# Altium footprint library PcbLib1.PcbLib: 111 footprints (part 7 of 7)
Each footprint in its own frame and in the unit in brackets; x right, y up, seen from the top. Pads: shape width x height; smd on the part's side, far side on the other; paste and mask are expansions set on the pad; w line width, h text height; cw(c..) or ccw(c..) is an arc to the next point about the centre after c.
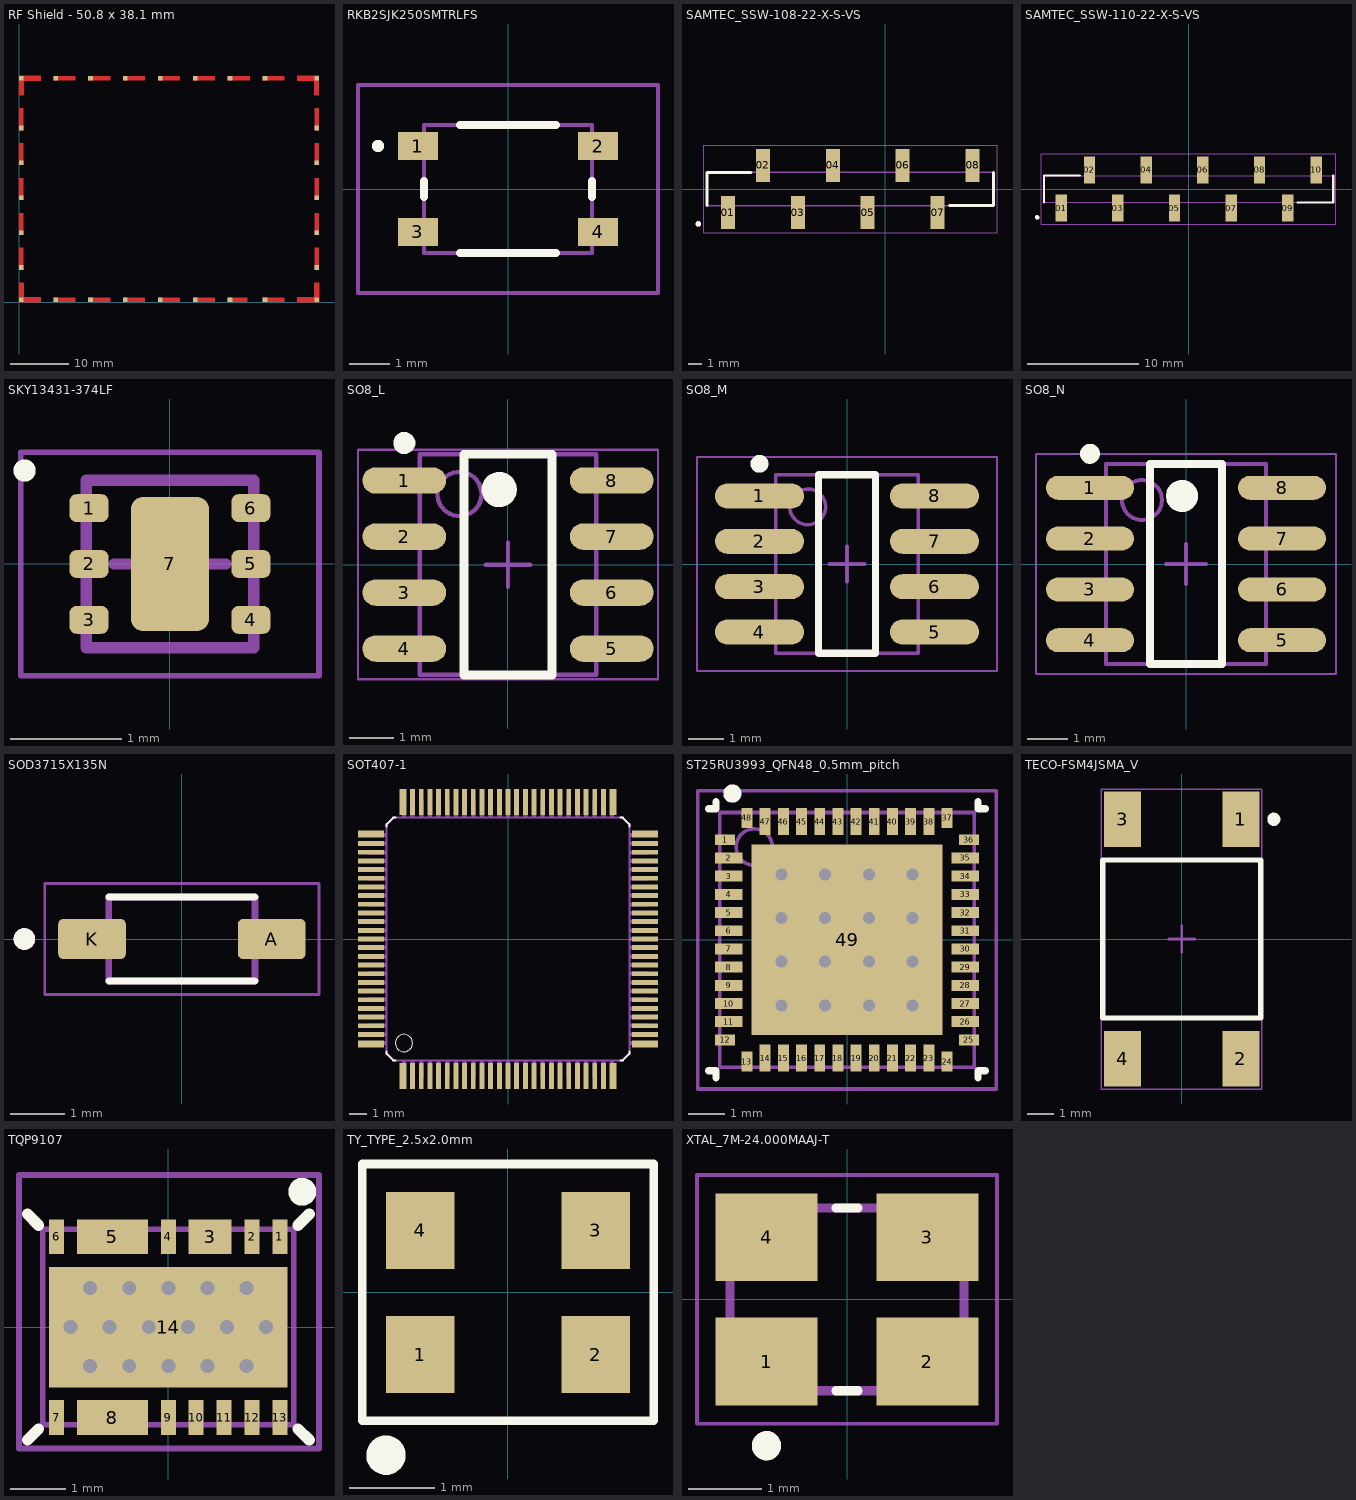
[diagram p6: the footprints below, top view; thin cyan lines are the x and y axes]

## RF Shield - 50.8 x 38.1 mm [mm] "2118732-2"
height 5.08
pads (28):
  rect 0.8x0.8 smd: 1(0.4,0.4) 2(0.4,5.95) 3(0.4,11.95) 4(0.4,17.95) 5(0.4,23.95) 6(0.4,29.95) 7(0.4,38.5) 8(6.3,38.5) 9(12.3,38.5) 10(18.3,38.5) 11(24.3,38.5) 12(30.3,38.5) 13(36.3,38.5) 14(42.3,38.5) 15(51.2,38.5) 16(51.2,29.95) 17(51.2,23.95) 18(51.2,17.95) 19(51.2,11.95) 20(51.2,5.95) 21(51.2,0.4) 22(42.3,0.4) 23(36.3,0.4) 24(30.3,0.4) 25(24.3,0.4) 26(18.3,0.4) 27(12.3,0.4) 28(6.3,0.4)
Top Layer:
  rectangle: 35.9,38.1 39.7,38.9
  rectangle: 29.9,38.1 33.7,38.9
  rectangle: 23.9,38.1 27.7,38.9
  rectangle: 17.9,38.1 21.7,38.9
  rectangle: 11.9,38.1 15.7,38.9
  rectangle: 5.9,38.1 9.7,38.9
  rectangle: 41.9,38.1 45.7,38.9
  rectangle: 50.8,29.55 51.6,33.35
  rectangle: 50.8,23.55 51.6,27.35
  rectangle: 50.8,17.55 51.6,21.35
  rectangle: 50.8,11.55 51.6,15.35
  rectangle: 50.8,5.55 51.6,9.35
  rectangle: 41.9,0 45.7,0.8
  rectangle: 0,23.55 0.8,27.35
  rectangle: 0,17.55 0.8,21.35
  rectangle: 0,11.55 0.8,15.35
  rectangle: 0,5.55 0.8,9.35
  rectangle: 5.9,0 9.7,0.8
  rectangle: 11.9,0 15.7,0.8
  rectangle: 17.9,0 21.7,0.8
  rectangle: 23.9,0 27.7,0.8
  rectangle: 29.9,0 33.7,0.8
  rectangle: 35.9,0 39.3,0.8
  rectangle: 0,29.55 0.8,33.35
  region: 51.6,38.899 51.6,35.55 50.8,35.55 50.8,38.1 47.899,38.1 47.899,38.899
  region: 51.6,0 51.6,3.3 50.8,3.3 50.8,0.8 47.9,0.8 47.9,0
  region: 0,0 0,3.35 0.8,3.35 0.8,0.8 3.7,0.8 3.7,0
  region: 0,38.9 0,35.55 0.8,35.55 0.8,38.1 3.701,38.1 3.701,38.9
3D body: height 5.08, standoff 4.88, extent 1.9,18.8 2.9,19.45
3D body: height 5.08, standoff 4.88, extent 1.9,19.45 2.9,20.1
3D body: height 5.08, standoff 4.88, extent 25.8,36 26.45,37
3D body: height 5.08, standoff 4.88, extent 25.15,36 25.8,37
3D body: height 5.08, standoff 4.88, extent 25.15,1.9 25.8,2.9
3D body: height 5.08, standoff 4.88, extent 25.8,1.9 26.45,2.9
3D body: height 5.08, standoff 4.88, extent 48.7,18.8 49.7,19.45
3D body: height 5.08, standoff 4.88, extent 48.7,19.45 49.7,20.1
3D body: height 5.08, standoff 4.88, extent 2.9,18.8 48.7,20.1
3D body: height 5.08, standoff 4.88, extent 25.15,2.9 26.45,36
3D body: height 5.08, standoff 4.88, extent 47.4,0.6 51,4.2
3D body: height 5.08, standoff 4.88, extent 47.4,34.7 51,38.3
3D body: height 5.08, standoff 4.88, extent 0.6,34.7 4.2,38.3
3D body: height 5.08, standoff 4.88, extent 0.6,1.9 1.9,37
3D body: height 5.08, standoff 4.88, extent 49.7,2.187 51,37
3D body: height 5.08, standoff 4.88, extent 0.6,37 51,38.3
3D body: height 5.08, standoff 4.88, extent 0.6,0.6 49.425,1.9
3D body: height 5.08, standoff 4.88, extent 0.6,0.6 4.2,4.2
3D body: height 0.51, standoff 0, extent 51,5.95 51.2,8.95
3D body: height 0.51, standoff 0, extent 51,11.95 51.2,14.95
3D body: height 0.51, standoff 0, extent 51,17.95 51.2,20.95
3D body: height 0.51, standoff 0, extent 51,23.95 51.2,26.95
3D body: height 0.51, standoff 0, extent 51,29.95 51.2,32.95
3D body: height 0.51, standoff 0, extent 50.999,35.95 51.199,38.5
3D body: height 0.51, standoff 0, extent 51,0.4 51.2,2.95
3D body: height 5.08, standoff 0.5, extent 51,0.4 51.2,38.5
3D body: height 5.08, standoff 0.5, extent 0.4,0.4 0.6,38.5
3D body: height 0.51, standoff 0, extent 0.4,0.4 0.6,2.95
3D body: height 0.51, standoff 0, extent 0.401,35.95 0.601,38.5
3D body: height 0.51, standoff 0, extent 0.4,29.95 0.6,32.95
3D body: height 0.51, standoff 0, extent 0.4,23.95 0.6,26.95
3D body: height 0.51, standoff 0, extent 0.4,17.95 0.6,20.95
3D body: height 0.51, standoff 0, extent 0.4,11.95 0.6,14.95
3D body: height 0.51, standoff 0, extent 0.4,5.95 0.6,8.95
3D body: height 5.08, standoff 0.5, extent 0.4,38.3 51.2,38.5
3D body: height 0.51, standoff 0, extent 0.4,38.3 3.3,38.5
3D body: height 0.51, standoff 0, extent 48.3,38.3 51.2,38.5
3D body: height 0.51, standoff 0, extent 6.3,38.3 9.3,38.5
3D body: height 0.51, standoff 0, extent 12.3,38.3 15.3,38.5
3D body: height 0.51, standoff 0, extent 18.3,38.3 21.3,38.5
3D body: height 0.51, standoff 0, extent 24.3,38.3 27.3,38.5
3D body: height 0.51, standoff 0, extent 30.3,38.3 33.3,38.5
3D body: height 0.51, standoff 0, extent 35.9,38.3 38.9,38.5
3D body: height 0.51, standoff 0, extent 42.3,38.3 45.3,38.5
3D body: height 0.51, standoff 0, extent 42.3,0.4 45.3,0.6
3D body: height 0.51, standoff 0, extent 35.9,0.4 38.9,0.6
3D body: height 0.51, standoff 0, extent 30.3,0.4 33.3,0.6
3D body: height 0.51, standoff 0, extent 24.3,0.4 27.3,0.6
3D body: height 0.51, standoff 0, extent 18.3,0.4 21.3,0.6
3D body: height 0.51, standoff 0, extent 12.3,0.4 15.3,0.6
3D body: height 0.51, standoff 0, extent 6.3,0.4 9.3,0.6
3D body: height 0.51, standoff 0, extent 48.3,0.4 51.2,0.6
3D body: height 0.51, standoff 0, extent 0.4,0.4 3.3,0.6
3D body: height 5.08, standoff 0.5, extent 0.4,0.4 51.2,0.6
3D body: height 5.08, standoff 4.88, extent 22.8,16.45 28.8,22.45
3D body: height 5.08, standoff 4.88, extent 49.425,0.6 51,2.187

## RKB2SJK250SMTRLFS [mm]
pads (4):
  rect 1x0.7 smd: 1(-2.25,1.075) 2(2.25,1.075) 3(-2.25,-1.075) 4(2.25,-1.075)
Top Overlay:
  lines w0.2: -3.3,1.075 ccw(c-3.25,1.075) -3.2,1.075 ; -3.3,1.075 cw(c-3.25,1.075) -3.2,1.075 ; -3.3,1.075 ccw(c-3.25,1.075) -3.2,1.075 ; -2.1,-0.2 -2.1,0.2 -2.1,-0.2 ; -1.2,-1.6 1.2,-1.6 -1.2,-1.6 ; -1.2,1.6 1.2,1.6 -1.2,1.6 ; 2.1,-0.2 2.1,0.2 2.1,-0.2
Mechanical 13:
  lines w0.1: -2.1,-1.6 2.1,-1.6 2.1,1.6 -2.1,1.6 -2.1,-1.6
Mechanical 15:
  lines w0.1: -3.75,-2.6 3.75,-2.6 3.75,2.6 -3.75,2.6 -3.75,-2.6
3D body "RKB2SJK250SMTR_LFS.stp": height 2.8, standoff 0, extent -2.68,-1.6 2.68,1.6

## SAMTEC_SSW-108-22-X-S-VS [mm]
pads (8):
  rect 1.02x2.41 smd: 01(-11.43,-1.715) 02(-8.89,1.715) 03(-6.35,-1.715) 04(-3.81,1.715) 05(-1.27,-1.715) 06(1.27,1.715) 07(3.81,-1.715) 08(6.35,1.715)
Top Overlay:
  circle w0.2: c-13.58,-2.54 r0.1
  lines w0.2: -12.955,-1.205 -12.955,1.205 -9.75,1.205 ; 4.67,-1.205 7.875,-1.205 7.875,1.205
Mechanical 13:
  circle w0.2: c-13.58,-2.54 r0.1
  lines w0.1: -12.955,-1.205 7.874,-1.205 7.874,1.205 -12.955,1.205 -12.955,-1.205
Mechanical 15:
  lines w0.05: -13.205,-3.17 8.128,-3.17 8.128,3.17 -13.205,3.17 -13.205,-3.17
3D body "SSW-108-22-F-S-VS.stp": height 9.76, standoff -0.02, extent -12.954,-2.578 7.874,2.578

## SAMTEC_SSW-110-22-X-S-VS [mm]
pads (10):
  rect 1.02x2.41 smd: 01(-11.43,-1.715) 02(-8.89,1.715) 03(-6.35,-1.715) 04(-3.81,1.715) 05(-1.27,-1.715) 06(1.27,1.715) 07(3.81,-1.715) 08(6.35,1.715) 09(8.89,-1.715) 10(11.43,1.715)
Top Overlay:
  circle w0.2: c-13.58,-2.54 r0.1
  lines w0.2: -12.955,-1.205 -12.955,1.205 -9.75,1.205 ; 9.75,-1.205 12.955,-1.205 12.955,1.205
Mechanical 13:
  circle w0.2: c-13.58,-2.54 r0.1
  lines w0.1: -12.955,-1.205 12.955,-1.205 12.955,1.205 -12.955,1.205 -12.955,-1.205
Mechanical 15:
  lines w0.05: -13.205,-3.17 13.205,-3.17 13.205,3.17 -13.205,3.17 -13.205,-3.17

## SKY13431-374LF [mm] "6 Pin DFN"
height 0.5
pads (7):
  rrect50% 0.35x0.25 smd mask+0.05: 1(-0.725,0.5) 2(-0.725,0) 3(-0.725,-0.5) 4(0.725,-0.5) 5(0.725,0) 6(0.725,0.5)
  rrect30% 0.7x1.2 smd mask+0.05: 7(0,0)
Top Overlay:
  circle w0.1: c-1.302,0.837 r0.05
Mechanical 13:
  lines w0.1: -0.75,-0.75 -0.75,0.75 0.75,0.75 0.75,-0.75 -0.75,-0.75
Mechanical 15:
  lines w0.05: -1.335,-1 -1.335,1 1.335,1 1.335,-1 -1.335,-1
  lines w0.1: -0.5,0 0.5,0 ; 0,-0.5 0,0.5
3D body: height 0.5, standoff 0, extent -0.75,-0.75 0.75,0.75

## SO8_L [mm] "SOIC, 8-Leads, Body 4.9x3.9mm, Pitch 1.27mm, IPC High Density"
height 1.75
pads (8):
  oval 1.9x0.6 smd: 1(-2.35,1.905) 2(-2.35,0.635) 3(-2.35,-0.635) 4(-2.35,-1.905) 5(2.35,-1.905) 6(2.35,-0.635) 7(2.35,0.635) 8(2.35,1.905)
Top Overlay:
  circle w0.4: c-0.2,1.7 r0.2
  circle w0.25: c-2.35,2.755 r0.125
  lines w0.2: -1,-2.5 1,-2.5 1,2.5 -1,2.5 -1,-2.5
Mechanical 13:
  circle w0.1: c-1.1,1.6 r0.5
  lines w0.1: -2,-2.5 2,-2.5 2,2.5 -2,2.5 -2,-2.5
Mechanical 15:
  lines w0.05: -3.4,-2.6 3.4,-2.6 3.4,2.6 -3.4,2.6 -3.4,-2.6
  lines w0.1: -0.5,0 0.5,0 ; 0,-0.5 0,0.5
3D body: height 1.75, standoff 0.1, extent -2,-2.5 2,2.5

## SO8_M [mm] "SOIC, 8-Leads, Body 4.9x3.9mm, Pitch 1.27mm, IPC Low Density"
height 1.75
pads (8):
  oval 2.5x0.7 smd: 1(-2.45,1.905) 2(-2.45,0.635) 3(-2.45,-0.635) 4(-2.45,-1.905) 5(2.45,-1.905) 6(2.45,-0.635) 7(2.45,0.635) 8(2.45,1.905)
Top Overlay:
  circle w0.25: c-2.45,2.805 r0.125
  lines w0.2: -0.8,-2.5 -0.8,2.5 0.8,2.5 0.8,-2.5 -0.8,-2.5
Mechanical 13:
  circle w0.1: c-1.1,1.6 r0.5
  lines w0.1: -2,-2.5 -2,2.5 2,2.5 2,-2.5 -2,-2.5
Mechanical 15:
  lines w0.05: -4.2,-3 -4.2,3 4.2,3 4.2,-3 -4.2,-3
  lines w0.1: -0.5,0 0.5,0 ; 0,-0.5 0,0.5
3D body: height 1.75, standoff 0.1, extent -2,-2.5 2,2.5

## SO8_N [mm] "SOIC, 8-Leads, Body 4.9x3.9mm, Pitch 1.27mm, IPC Medium Density"
height 1.75
pads (8):
  oval 2.2x0.6 smd: 1(-2.4,1.905) 2(-2.4,0.635) 3(-2.4,-0.635) 4(-2.4,-1.905) 5(2.4,-1.905) 6(2.4,-0.635) 7(2.4,0.635) 8(2.4,1.905)
Top Overlay:
  circle w0.4: c-0.1,1.7 r0.2
  circle w0.25: c-2.4,2.755 r0.125
  lines w0.2: -0.9,-2.5 0.9,-2.5 0.9,2.5 -0.9,2.5 -0.9,-2.5
Mechanical 13:
  circle w0.1: c-1.1,1.6 r0.5
  lines w0.1: -2,-2.5 2,-2.5 2,2.5 -2,2.5 -2,-2.5
Mechanical 15:
  lines w0.05: -3.75,-2.75 3.75,-2.75 3.75,2.75 -3.75,2.75 -3.75,-2.75
  lines w0.1: -0.5,0 0.5,0 ; 0,-0.5 0,0.5
3D body: height 1.75, standoff 0.1, extent -2,-2.5 2,2.5

## SOD3715X135N [mm]
pads (2):
  rrect25% 1.25x0.74 smd: A(1.66,0) K(-1.66,0)
Top Overlay:
  circle w0.2: c-2.91,0 r0.1
  lines w0.127: -1.35,-0.775 1.35,-0.775 ; -1.35,0.775 1.35,0.775
Mechanical 13:
  circle w0.2: c-2.91,0 r0.1
  lines w0.127: -1.35,-0.775 1.35,-0.775 1.35,0.775 -1.35,0.775 -1.35,-0.775
Mechanical 15:
  lines w0.05: -2.535,-1.025 2.535,-1.025 2.535,1.025 -2.535,1.025 -2.535,-1.025
3D body "BAT54W-HG3-18.STEP": height 1.41, standoff -0.04, extent -1.85,-0.775 1.85,0.775

## SOT407-1 [mm]
pads (100):
  rect 0.4x1.5 smd: 1(-6.06,-7.9) 25(6.06,-7.9) 51(6.06,7.9) 75(-6.06,7.9)
  rect 0.28x1.5 smd: 2(-5.5,-7.9) 3(-5,-7.9) 4(-4.5,-7.9) 5(-4,-7.9) 6(-3.5,-7.9) 7(-3,-7.9) 8(-2.5,-7.9) 9(-2,-7.9) 10(-1.5,-7.9) 11(-1,-7.9) 12(-0.5,-7.9) 13(0,-7.9) 14(0.5,-7.9) 15(1,-7.9) 16(1.5,-7.9) 17(2,-7.9) 18(2.5,-7.9) 19(3,-7.9) 20(3.5,-7.9) 21(4,-7.9) 22(4.5,-7.9) 23(5,-7.9) 24(5.5,-7.9) 52(5.5,7.9) 53(5,7.9) 54(4.5,7.9) 55(4,7.9) 56(3.5,7.9) 57(3,7.9) 58(2.5,7.9) 59(2,7.9) 60(1.5,7.9) 61(1,7.9) 62(0.5,7.9) 63(0,7.9) 64(-0.5,7.9) 65(-1,7.9) 66(-1.5,7.9) 67(-2,7.9) 68(-2.5,7.9) 69(-3,7.9) 70(-3.5,7.9) 71(-4,7.9) 72(-4.5,7.9) 73(-5,7.9) 74(-5.5,7.9)
  rect 1.5x0.4 smd: 26(7.9,-6.06) 50(7.9,6.06) 76(-7.9,6.06) 100(-7.9,-6.06)
  rect 1.5x0.28 smd: 27(7.9,-5.5) 28(7.9,-5) 29(7.9,-4.5) 30(7.9,-4) 31(7.9,-3.5) 32(7.9,-3) 33(7.9,-2.5) 34(7.9,-2) 35(7.9,-1.5) 36(7.9,-1) 37(7.9,-0.5) 38(7.9,0) 39(7.9,0.5) 40(7.9,1) 41(7.9,1.5) 42(7.9,2) 43(7.9,2.5) 44(7.9,3) 45(7.9,3.5) 46(7.9,4) 47(7.9,4.5) 48(7.9,5) 49(7.9,5.5) 77(-7.9,5.5) 78(-7.9,5) 79(-7.9,4.5) 80(-7.9,4) 81(-7.9,3.5) 82(-7.9,3) 83(-7.9,2.5) 84(-7.9,2) 85(-7.9,1.5) 86(-7.9,1) 87(-7.9,0.5) 88(-7.9,0) 89(-7.9,-0.5) 90(-7.9,-1) 91(-7.9,-1.5) 92(-7.9,-2) 93(-7.9,-2.5) 94(-7.9,-3) 95(-7.9,-3.5) 96(-7.9,-4) 97(-7.9,-4.5) 98(-7.9,-5) 99(-7.9,-5.5)
Top Overlay:
  circle w0: c-6,-6 r0.5
  lines w0.127: -7,-6.5 -7,-6.625 -6.625,-7 -6.5,-7 ; -7,6.5 -7,6.625 -6.625,7 -6.5,7 ; 6.5,-7 6.625,-7 7,-6.625 7,-6.5 ; 6.5,7 6.625,7 7,6.625 7,6.5
Mechanical 13:
  drawing of 108 lines, arcs and shapes, not listed
3D body "step_temp.STEP": height 0.75, standoff -0.95, extent -8,-8 8,8

## ST25RU3993_QFN48_0.5mm_pitch [mm] "QFN, 48-Leads, Body 7,0x7,0mm (max), Pitch 0,50mm, IPC Medium Density"
height 1
pads (49):
  rect 0.55x0.3 smd paste+0 mask+0.05: 1(-3.35,2.75) 12(-3.35,-2.75) 25(3.35,-2.75) 36(3.35,2.75)
  rect 0.75x0.3 smd mask+0.05: 2(-3.25,2.25)
  rect 0.75x0.3 smd paste+0 mask+0.05: 3(-3.25,1.75) 4(-3.25,1.25) 5(-3.25,0.75) 6(-3.25,0.25) 7(-3.25,-0.25) 8(-3.25,-0.75) 9(-3.25,-1.25) 10(-3.25,-1.75) 11(-3.25,-2.25) 26(3.25,-2.25) 27(3.25,-1.75) 28(3.25,-1.25) 29(3.25,-0.75) 30(3.25,-0.25) 31(3.25,0.25) 32(3.25,0.75) 33(3.25,1.25) 34(3.25,1.75) 35(3.25,2.25)
  rect 0.3x0.55 smd paste+0 mask+0.05: 13(-2.75,-3.35) 24(2.75,-3.35) 37(2.75,3.35) 48(-2.75,3.35)
  rect 0.3x0.75 smd paste+0 mask+0.05: 14(-2.25,-3.25) 15(-1.75,-3.25) 16(-1.25,-3.25) 17(-0.75,-3.25) 18(-0.25,-3.25) 19(0.25,-3.25) 20(0.75,-3.25) 21(1.25,-3.25) 22(1.75,-3.25) 23(2.25,-3.25) 38(2.25,3.25) 39(1.75,3.25) 40(1.25,3.25) 41(0.75,3.25) 42(0.25,3.25) 43(-0.25,3.25) 44(-0.75,3.25) 45(-1.25,3.25) 46(-1.75,3.25) 47(-2.25,3.25)
  rect 5.24x5.24 smd mask+0.07: 49(0,0)
via -1.8,-0.6 diameter 0.66 hole 0.33
via -0.6,-0.6 diameter 0.66 hole 0.33
via 0.6,-0.6 diameter 0.66 hole 0.33
via 1.8,-0.6 diameter 0.66 hole 0.33
via -1.8,-1.8 diameter 0.66 hole 0.33
via -0.6,-1.8 diameter 0.66 hole 0.33
via 0.6,-1.8 diameter 0.66 hole 0.33
via 1.8,-1.8 diameter 0.66 hole 0.33
via -0.6,1.8 diameter 0.66 hole 0.33
via 0.6,1.8 diameter 0.66 hole 0.33
via -1.8,1.8 diameter 0.66 hole 0.33
via 1.8,0.6 diameter 0.66 hole 0.33
via 0.6,0.6 diameter 0.66 hole 0.33
via -0.6,0.6 diameter 0.66 hole 0.33
via -1.8,0.6 diameter 0.66 hole 0.33
via 1.8,1.8 diameter 0.66 hole 0.33
Top Overlay:
  circle w0.25: c-3.15,4.021 r0.125
  lines w0.2: -3.8,-3.6 -3.6,-3.6 -3.6,-3.8 ; -3.8,3.6 -3.6,3.6 -3.6,3.8 ; 3.6,-3.8 3.6,-3.6 3.8,-3.6 ; 3.6,3.8 3.6,3.6 3.8,3.6
Mechanical 13:
  circle w0.1: c-2.55,2.55 r0.5
  lines w0.1: -3.5,-3.5 -3.5,3.5 3.5,3.5 3.5,-3.5 -3.5,-3.5
Mechanical 15:
  lines w0.1: -0.5,0 0.5,0 ; 0,-0.5 0,0.5 ; -4.1,-4.1 -4.1,4.1 4.1,4.1 4.1,-4.1 -4.1,-4.1
3D body "as3993.stp": height 0.9, standoff 0, extent -3.503,-3.503 3.503,3.503
3D body: height 1, standoff 0, extent -3.495,-3.494 3.488,3.493

## TECO-FSM4JSMA_V [mm] "SMD, 4-Leads, Body 6x6mm, Pitch 4.5mm"
height 5.23
pads (4):
  rect 1.4x2.1 smd: 1(2.25,4.55) 2(2.25,-4.55) 3(-2.25,4.55) 4(-2.25,-4.55)
Top Overlay:
  circle w0.25: c3.5,4.55 r0.125
  lines w0.2: -3,-3 3,-3 3,3 -3,3 -3,-3
Mechanical 13:
  lines w0.1: -3,-3 -3,3 3,3 3,-3 -3,-3
Mechanical 15:
  lines w0.05: -3.05,-5.7 -3.05,5.7 3.05,5.7 3.05,-5.7 -3.05,-5.7
  lines w0.1: -0.5,0 0.5,0 ; 0,-0.5 0,0.5
3D body "c-4-1437565-2-s-3d.stp": height 5.08, standoff 0, extent -3,-5 3,5

## TQP9107 [mm] "699 – 960 MHz 2-stage Power Amplifier"
height 1
pads (14):
  rect 0.27x0.62 smd mask+0.05: 1(2,1.62) 2(1.5,1.62) 4(0,1.62) 6(-2,1.62) 7(-2,-1.62) 9(0,-1.62) 10(0.5,-1.62) 11(1,-1.62) 12(1.5,-1.62) 13(2,-1.62)
  rect 0.77x0.62 smd mask+0.05: 3(0.75,1.62)
  rect 1.27x0.62 smd mask+0.05: 5(-1,1.62) 8(-1,-1.62)
  rect 4.28x2.16 smd mask+0.05: 14(0,0)
via 1.4,-0.7 diameter 0.6 hole 0.25
via 1.4,0.7 diameter 0.6 hole 0.25
via 0.7,0.7 diameter 0.6 hole 0.25
via 0.7,-0.7 diameter 0.6 hole 0.25
via -1.4,-0.7 diameter 0.6 hole 0.25
via -0.7,-0.7 diameter 0.6 hole 0.25
via -1.4,0.7 diameter 0.6 hole 0.25
via -0.7,0.7 diameter 0.6 hole 0.25
via -1.75,0 diameter 0.6 hole 0.25
via -1.05,0 diameter 0.6 hole 0.25
via 1.75,0 diameter 0.6 hole 0.25
via 0,0.7 diameter 0.6 hole 0.25
via 0,-0.7 diameter 0.6 hole 0.25
via 1.05,0 diameter 0.6 hole 0.25
via -0.35,0 diameter 0.6 hole 0.25
via 0.35,0 diameter 0.6 hole 0.25
Top Overlay:
  circle w0.25: c2.4,2.425 r0.125
  lines w0.2: -2.525,-2.025 -2.325,-1.825 ; -2.525,2.025 -2.325,1.825 ; 2.325,-1.825 2.525,-2.025 ; 2.325,1.825 2.525,2.025
Mechanical 13:
  lines w0.1: -2.25,-1.75 2.25,-1.75 2.25,1.75 -2.25,1.75 -2.25,-1.75
Mechanical 15:
  lines w0.1: -0.5,0 0.5,0 ; 0,-0.5 0,0.5 ; -2.675,-2.175 2.7,-2.175 2.7,2.725 -2.675,2.725 -2.675,-2.175
3D body: height 0.85, standoff 0, extent -2.25,-1.75 2.25,1.75

## TY_TYPE_2.5x2.0mm [mm] "TCXO package Taitien TY type"
pads (4):
  rect 0.8x0.9 smd: 1(-1.025,-0.725) 2(1.025,-0.725) 3(1.025,0.725) 4(-1.025,0.725)
Top Overlay:
  lines w0.1: -1.7,-1.5 1.7,-1.5 1.7,1.5 0,1.5 -1.7,1.5 -1.7,-1.5
  lines w0.254: -1.325,-1.877 ccw(c-1.425,-1.9) -1.322,-1.89

## XTAL_7M-24.000MAAJ-T [mm]
pads (4):
  rect 1.4x1.2 smd: 1(-1.1,-0.85) 2(1.1,-0.85) 3(1.1,0.85) 4(-1.1,0.85)
Top Overlay:
  circle w0.2: c-1.1,-2 r0.1
  lines w0.127: -0.15,-1.25 0.15,-1.25 ; -0.15,1.25 0.15,1.25
Mechanical 13:
  circle w0.2: c-1.1,-2 r0.1
  lines w0.127: -1.6,-1.25 -1.6,1.25 1.6,1.25 1.6,-1.25 -1.6,-1.25
Mechanical 15:
  lines w0.05: -2.05,-1.7 -2.05,1.7 2.05,1.7 2.05,-1.7 -2.05,-1.7
3D body: height 0.81, standoff 0, extent -1.6,-1.3 1.6,1.3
